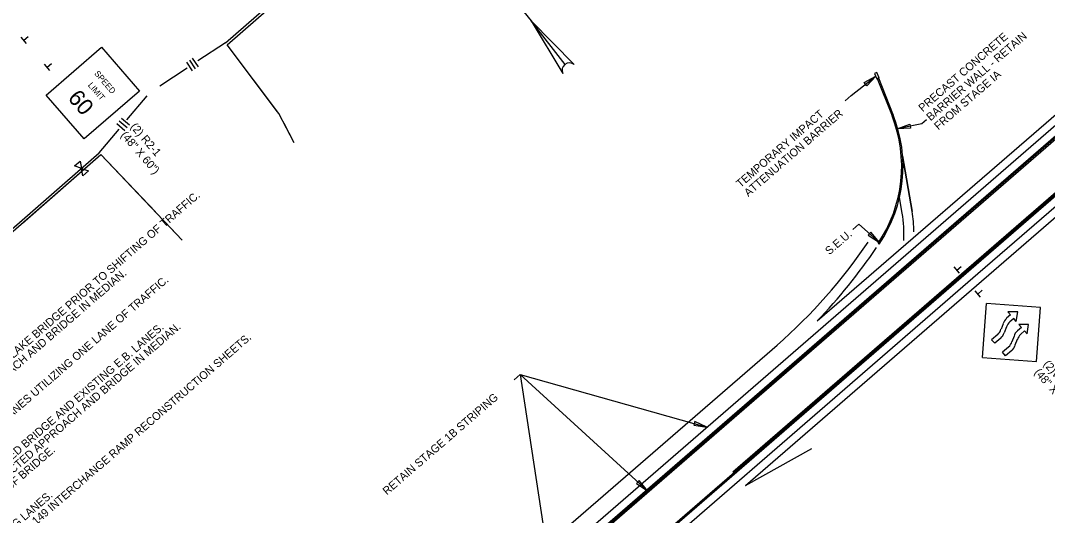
# Model space of a CAD drawing. Extents: x 259983 to 267998, y 211467 to 219827.
# Drawn here: x 262385 to 263924, y 215675 to 216417 of the extents above; entities that cross this region are included whole.
import ezdxf

# ---------------------------------------------------------------- set-up
doc = ezdxf.new("R2010")
doc.units = 0
for name, color, linetype in [('1', 7, 'Continuous'), ('Level 1', 7, 'Continuous'), ('R-W - CofA', 7, 'Continuous'), ('R_MOT', 7, 'Continuous'), ('R_MOT STAGE 1', 7, 'Continuous'), ('R_MOT STAGE 2', 7, 'Continuous'), ('ROAD', 7, 'Continuous')]:
    doc.layers.add(name, color=color, linetype=linetype)

msp = doc.modelspace()

# ---------------------------------------------------------------- linework, layer by layer
at = {"layer": '1'}
for p, q in [((263629.7, 216304.6), (263666.8, 216333.5)), ((263629.7, 216304.6), (263620.5, 216296.6)), ((263735.6, 216262), (263698.7, 216254.7)), ((263742.7, 216268.1), (263735.6, 216262)), ((263641.3, 216111.4), (263632.4, 216103.7)), ((263641.3, 216111.4), (263671.9, 216084)), ((263124.7, 215878.7), (263133.6, 215886.3)), ((263133.6, 215886.3), (263413.5, 215807.8))]:
    msp.add_line(p, q, dxfattribs=at)
for points in [[(263649.3, 216323.7), (263666.8, 216333.5), (263653, 216318.9)], [(263718.7, 216255.6), (263698.7, 216254.7), (263717.5, 216261.5)], [(263655.2, 216095.1), (263671.9, 216084), (263659.3, 216099.5)], [(263393.7, 215810.5), (263413.5, 215807.8), (263395.3, 215816.2)], [(263307.8, 215723.3), (263324.4, 215712.2), (263311.8, 215727.7)]]:
    msp.add_lwpolyline(points, close=True, dxfattribs=at)
at = {"layer": 'Level 1'}
for p, q in [((263139.1, 216429.8), (263149.8, 216416)), ((263149.8, 216416), (263197.6, 216337.3)), ((263200.8, 216350.8), (263149.8, 216416)), ((263149.8, 216416), (263214.7, 216350.7))]:
    msp.add_line(p, q, dxfattribs=at)
for start, end in [(128, 205.3196), (50.6804, 128)]:
    msp.add_arc((263207.6, 216342), 11.2, start, end, dxfattribs=at)
at = {"layer": 'R-W - CofA'}
for p, q in [((262691.6, 216383.4), (262650.4, 216356.1)), ((262642.5, 216341.4), (262633.9, 216354.4)), ((262646.8, 216344.3), (262638.2, 216357.3)), ((262651.2, 216347.2), (262642.5, 216360.2)), ((262634.6, 216345.5), (262593.4, 216318.2)), ((262529.1, 216262.2), (262541.1, 216252.2)), ((262532.5, 216266.2), (262544.4, 216256.2)), ((262535.8, 216270.2), (262547.8, 216260.2)), ((262465.3, 216198.8), (262473.8, 216206.2)), ((262475.9, 216195.2), (262465.3, 216198.8)), ((262473.8, 216206.2), (262475.9, 216195.2)), ((262478.1, 216184.2), (262475.9, 216195.2)), ((262475.9, 216195.2), (262486.6, 216191.6)), ((262486.6, 216191.6), (262478.1, 216184.2))]:
    msp.add_line(p, q, dxfattribs=at)
for points in [[(262694.2, 216380.4), (263719.6, 217273.9)], [(262691.6, 216383.4), (262947.2, 216606.1)], [(262694.2, 216380.4), (262811.8, 216482.9)], [(262769.3, 216280.5), (262694.2, 216380.4)], [(262795, 216233.6), (262771.7, 216277.2), (262694.2, 216380.4)], [(262544.1, 216267.9), (262574.2, 216303.7)], [(262773.8, 216273.3), (262771.7, 216277.2), (262771.6, 216277.4)], [(262777.9, 216265.8), (262775.7, 216269.9)], [(262795, 216233.6), (262779.7, 216262.3)], [(262502.7, 216218.6), (262532.6, 216254.2)], [(261908.1, 215682.2), (261969.3, 215735.5), (262038.1, 215808.8), (262505.2, 216215.8)], [(262251.8, 216000), (262502.7, 216218.6)], [(262387.5, 216113.2), (262505.2, 216215.8)], [(262505.2, 216215.8), (262586.7, 216130)], [(262505.2, 216215.8), (262626.7, 216087.9)], [(262589.3, 216127.2), (262592.5, 216123.9)], [(262595.1, 216121.1), (262598.3, 216117.8)], [(262600.9, 216115.1), (262626.7, 216087.9)]]:
    msp.add_lwpolyline(points, dxfattribs=at)
at = {"layer": 'R_MOT'}
for p, q in [((262393.4, 216382.5), (262385.4, 216391.7)), ((262389.4, 216387.1), (262395.8, 216392.6)), ((262428.4, 216342), (262420.4, 216351.2)), ((262424.4, 216346.6), (262430.9, 216352.1)), ((263792.3, 216038.2), (263784.3, 216047.5)), ((263788.3, 216042.8), (263794.8, 216048.4)), ((263823.4, 216002.4), (263815.4, 216011.6)), ((263819.4, 216007), (263825.8, 216012.6)), ((263826.7, 215911.8), (263832.4, 215992.6)), ((263913.3, 215986.8), (263832.5, 215992.7)), ((263879.3, 215980.5), (263864.7, 215980.4)), ((263868.6, 215975.9), (263864.7, 215980.4)), ((263877.2, 215966), (263879.3, 215980.5)), ((263907.4, 215906.1), (263913.3, 215986.8)), ((263868.6, 215975.9), (263862.5, 215970.6)), ((263873.3, 215970.5), (263867.5, 215965.5)), ((263877.2, 215966), (263873.3, 215970.5)), ((263857.5, 215962.6), (263854.3, 215954.5)), ((263862.4, 215957.7), (263858.9, 215949.1)), ((263884.9, 215957), (263878.8, 215951.7)), ((263895.7, 215961.6), (263881.1, 215961.5)), ((263884.9, 215957), (263881.1, 215961.5)), ((263889.6, 215951.7), (263883.9, 215946.7)), ((263893.5, 215947.2), (263889.6, 215951.7)), ((263893.5, 215947.2), (263895.7, 215961.6)), ((263849.4, 215946.5), (263840.2, 215938.6)), ((263844.9, 215933.2), (263840.2, 215938.6)), ((263854, 215941.1), (263844.9, 215933.2)), ((263873.8, 215943.8), (263870.6, 215935.6)), ((263878.7, 215938.9), (263875.2, 215930.2)), ((263865.7, 215927.6), (263856.6, 215919.7)), ((263861.2, 215914.3), (263856.6, 215919.7)), ((263870.3, 215922.2), (263861.2, 215914.3)), ((263826.7, 215911.8), (263907.4, 215906.1))]:
    msp.add_line(p, q, dxfattribs=at)
msp.add_lwpolyline([(262562.8, 216311), (262480, 216239.4), (262423.1, 216305.1), (262506, 216376.8)], close=True, dxfattribs=at)
for centre, major_axis in [((263873.8, 215956.9), (-11.6, 13.4)), ((263878.9, 215951.9), (-11.6, 13.4)), ((263838, 215960.2), (11.6, -13.4)), ((263842.7, 215954.7), (11.6, -13.4)), ((263890.1, 215938.1), (-11.6, 13.4)), ((263854.3, 215941.3), (11.6, -13.4)), ((263895.2, 215933), (-11.6, 13.4)), ((263859, 215935.9), (11.6, -13.4))]:
    msp.add_ellipse(centre, major_axis=major_axis, ratio=0.9, start_param=6.26006, end_param=6.849246, dxfattribs=at)
at = {"layer": 'R_MOT STAGE 1'}
for p, q in [((263578.6, 215966.6), (264310.4, 216600.1)), ((264298.4, 216555.3), (263057.4, 215481)), ((264299.6, 216553.8), (263058.7, 215479.5)), ((263048.2, 215491.5), (264237, 216520.7)), ((263056, 215482.5), (264244.9, 216511.7)), ((263668.8, 216329.9), (263670.6, 216330.6)), ((263668.8, 216329.9), (263690.9, 216274.1)), ((263670.6, 216330.6), (263692.8, 216274.9)), ((263286.2, 215594.4), (264026.9, 216235.7)), ((263287.5, 215592.9), (264028.2, 216234.2)), ((263452.2, 215740.7), (264025.6, 216237.2)), ((263819.5, 216037.6), (264036.2, 216225.2)), ((263471.1, 215720.1), (264044.2, 216216.3)), ((263706.8, 216213.8), (263720.9, 216130.6)), ((263720.9, 216130.6), (263706.8, 216213.8)), ((263706.1, 216128.1), (263702.1, 216151.7)), ((263670, 216083.1), (263671.7, 216081.9)), ((263295.4, 215583.8), (263819.5, 216037.6)), ((263056.7, 215530.7), (263518.5, 215930.5)), ((263471.1, 215720.1), (263570.7, 215775.4))]:
    msp.add_line(p, q, dxfattribs=at)
msp.add_lwpolyline([(263671.4, 216330.9), (263668.2, 216338.7), (263664.7, 216337.2), (263667.9, 216329.5)], close=True, dxfattribs=at)
for centre, radius, start, end in [((263499.9, 216198.3), 205.5, 325.8833, 21.6456), ((263499.9, 216198.3), 207.5, 325.8833, 22.076), ((263516.3, 216096), 192.5, 357.3485, 9.5976), ((263516.3, 216096), 207.5, 1.1658, 9.5976), ((263000.4, 216526), 789.4, 311.0269, 326.027), ((262997.5, 216527.3), 807.5, 316.0285, 326.0667)]:
    msp.add_arc(centre, radius, start, end, dxfattribs=at)
at = {"layer": 'R_MOT STAGE 2'}
for p, q in [((263324.4, 215712.2), (263133.6, 215886.3)), ((263133.6, 215886.3), (263172.6, 215631))]:
    msp.add_line(p, q, dxfattribs=at)

# ---------------------------------------------------------------- texts
at = {"layer": '1'}
for s, rotation, p in [('PRECAST CONCRETE', 40.8833, (263736.9, 216279.2)), ('BARRIER WALL - RETAIN', 40.8833, (263748.7, 216265.6)), ('FROM STAGE IA', 40.8833, (263760.4, 216252)), ('TEMPORARY IMPACT', 40.8733, (263463.7, 216165.7)), ('ATTENUATION BARRIER', 40.8733, (263475.5, 216152.1)), ('S.E.U.', 40.8733, (263597, 216064.9)), ('RETAIN STAGE 1B STRIPING', 40.8733, (262933.8, 215705.2))]:
    msp.add_text(s, height=12, rotation=rotation, dxfattribs=at).set_placement(p)
at = {"layer": 'R_MOT'}
for s, height, rotation, p in [('SPEED', 9.05, 310.8555, (262494.5, 216336.9)), ('LIMIT', 9.05, 310.8555, (262484.9, 216319.4)), ('60', 24.26, 310.8555, (262454.3, 216299.9)), ('(2) R2-1', 12.13, 310.8555, (262548.5, 216257.1)), ('(48" X 60")', 12.129, 310.8555, (262534, 216244.5)), ('(2)W1-4bL', 12, 310.8833, (263917, 215901.6)), ('(48" X 48")', 12, 310.8833, (263903.4, 215889.2))]:
    msp.add_text(s, height=height, rotation=rotation, dxfattribs=at).set_placement(p)
at = {"layer": 'ROAD'}
for s, p in [('CONSTRUCT PORTION OF APPROACH ON OFF END OF SHELL LAKE BRIDGE PRIOR TO SHIFTING OF TRAFFIC.', (262003.6, 215589.6)), ('ROUTE I-40 E.B. TRAFFIC TO NEWLY CONSTRUCTED APPROACH AND BRIDGE IN MEDIAN.', (262014.2, 215577.3)), ('PLACE PORTION OF PAVEMENT TRANSITION ON E.B. LANES UTILIZING ONE LANE OF TRAFFIC.', (262046.1, 215540.5)), ('ROUTE I-40 E.B. TRAFFIC TO NEWLY CONSTRUCTED BRIDGE AND EXISTING E.B. LANES.', (262078, 215503.6)), ('ROUTE 1-40 W.B. TRAFFIC TO NEWLY CONSTRUCTED APPROACH AND BRIDGE IN MEDIAN.', (262088.7, 215491.3)), ('REFER TO MAINTENANCE OF TRAFFIC HWY. 149 INTERCHANGE RAMP RECONSTRUCTION SHEETS.', (262141.9, 215429.9)), ('CONSTRUCT APPROACH AND W.B. PORTION OF BRIDGE.', (262099.3, 215479)), ('ROUTE I-40 E.B. AND I-40 W.B. TO EXISTING LANES.', (262131.2, 215442.2))]:
    msp.add_text(s, height=12, rotation=40.8833, dxfattribs=at).set_placement(p)

doc.saveas('drawing.dxf')
